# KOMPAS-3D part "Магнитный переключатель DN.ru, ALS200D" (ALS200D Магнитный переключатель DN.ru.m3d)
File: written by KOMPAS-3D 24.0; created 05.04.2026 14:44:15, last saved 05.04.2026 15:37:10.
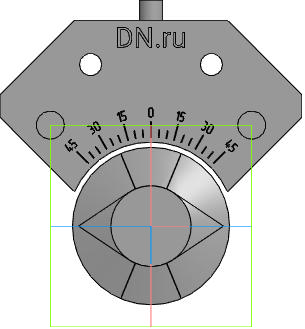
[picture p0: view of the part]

Document properties: Автор: R2D2; Полное имя файла: E:\Работа\Зайцев\Аксессуары для пневмоприводов\Электропневматические позиционеры DN.ru\ALS200D Магнитный переключатель DN.ru\ALS200D Магнитный переключатель DN.ru.m3d

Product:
- Part/product: Магнитный переключатель DN.ru  | designation ALS200D
    Масса: 0.14
    Раздел спецификации: Прочие изделия
    Примечание: D290-00318

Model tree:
1. Эскиз:1
2. Элемент выдавливания:1
     Расстояние 1 = 34
3. Эскиз:3  (with: Ребро.Элемент выдавливания:1)
4. Элемент вращения:1
     Угол 1 = 360
5. Эскиз:4  (with: Ребро.Элемент выдавливания:1, Грань.Элемент вращения:1)
6. Элемент вращения:2
     Угол 1 = 360
7. Эскиз:5
8. Элемент выдавливания:3  (with: Грань.Элемент вращения:1)
     Расстояние 1 = 32.07; Смещение 1 = 0.1
9. Зеркальный массив:1
10. Экземпляр ( 1 )
11. Экземпляр ( 2 )  (with: Элемент выдавливания:3)
12. Зеркальный массив:2  (with: Экземпляр ( 1 ), Экземпляр ( 2 ), Зеркальный массив:1, Элемент выдавливания:3)
13. Эскиз:6
14. Элемент выдавливания:4
     Расстояние 1 = 20
15. Эскиз:7  (with: Грань.Элемент выдавливания:4, Ребро.Элемент выдавливания:4)
16. Элемент выдавливания:5
     Расстояние 1 = 5
17. Эскиз:8  (with: Грань.Элемент выдавливания:4)
18. Элемент выдавливания:6
19. Эскиз:9  (with: Грань.Элемент выдавливания:4)
20. Элемент выдавливания:7
     Расстояние 1 = 0.5
21. Эскиз:10  (with: Грань.Элемент выдавливания:4)
22. Элемент выдавливания:8
     Расстояние 1 = 0.5
23. Массив по концентрической сетке:1  (with: Элемент выдавливания:8, Эскиз:10, Грань.Элемент вращения:1)  (10 pattern instances)
     Шаг 2 = 45
24. Массив по концентрической сетке:2  (with: Элемент выдавливания:8, Эскиз:10, Грань.Элемент вращения:1)  (10 pattern instances)
     Шаг 2 = 45
25. Эскиз:11  (with: Грань.Элемент выдавливания:4, Вершина.Элемент выдавливания:8, Ребро.Элемент выдавливания:8)
26. Элемент выдавливания:9
     Расстояние 1 = 0.5
27. Массив по концентрической сетке:3  (with: Элемент выдавливания:9, Грань.Элемент вращения:1)  (4 pattern instances)
     Шаг 2 = 15
28. Массив по концентрической сетке:4  (with: Элемент выдавливания:9, Грань.Элемент вращения:1)  (4 pattern instances)
     Шаг 2 = 15
29. Эскиз:12  (with: Грань.Элемент выдавливания:4)
30. Зеркальный массив:4  (with: Экземпляр ( 1 ), Экземпляр ( 2 ), Элемент выдавливания:7, Элемент выдавливания:6)
31. Элемент выдавливания:10
     Расстояние 1 = 0.5
32. Эскиз:13  (with: Грань.Элемент выдавливания:4)
33. Элемент выдавливания:11
     Расстояние 1 = 0.5

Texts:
  ALS200D
  Группа символов вдоль кривой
